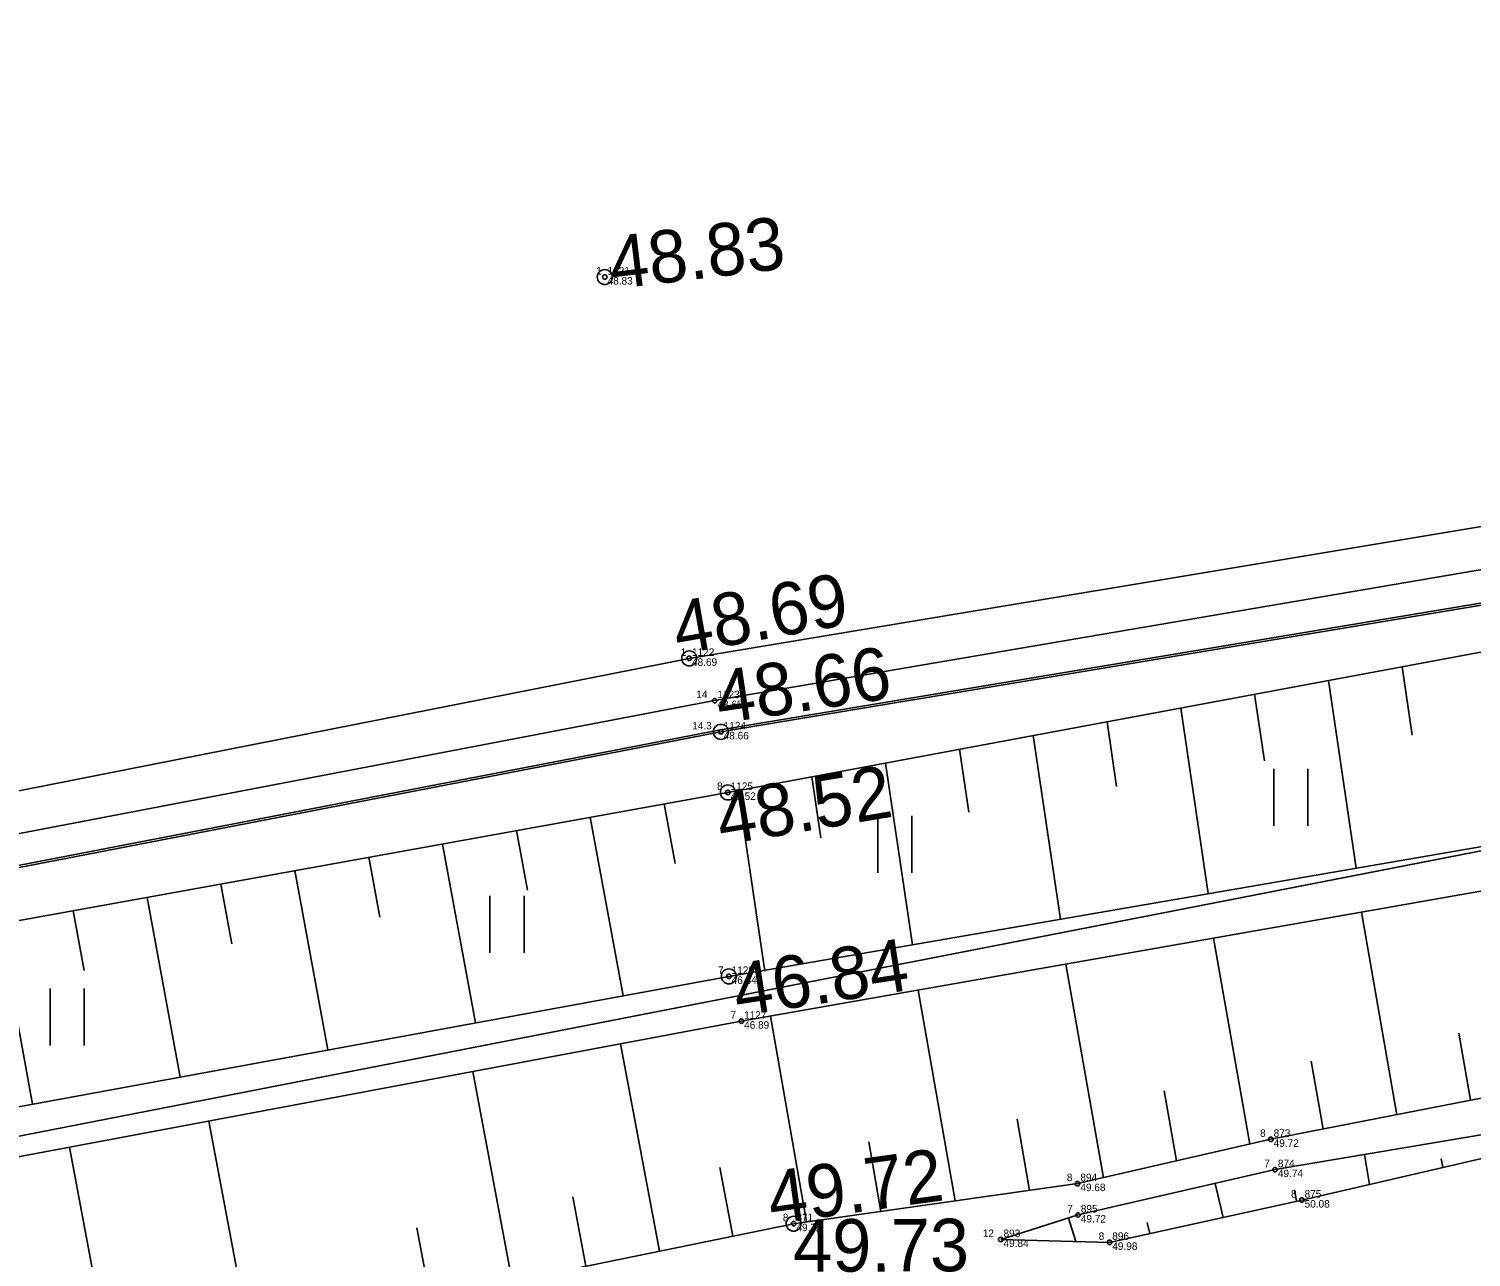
# Model space of a CAD drawing. Extents: x 543497 to 552146, y 6567125 to 6579845.
# Drawn here: x 546549.56 to 546568.77, y 6577774.51 to 6577790.87 of the extents above; entities that cross this region are included whole.
import ezdxf

# ---------------------------------------------------------------- set-up
doc = ezdxf.new("R2010")
doc.units = 0
for name, color, linetype in [('xref_Kangru tee 1_geodeesia$0$HALJASTUS', 7, 'Continuous'), ('xref_Kangru tee 1_geodeesia$0$korgus-EH2000', 7, 'Continuous'), ('xref_Kangru tee 1_geodeesia$0$Liiklus', 7, 'Continuous'), ('xref_Kangru tee 1_geodeesia$0$mootkood', 7, 'Continuous'), ('xref_Kangru tee 1_geodeesia$0$MOOTKORG-eh2000', 7, 'Continuous'), ('xref_Kangru tee 1_geodeesia$0$mootmpunkt', 7, 'Continuous'), ('xref_Kangru tee 1_geodeesia$0$MOOTNR', 7, 'Continuous'), ('xref_Kangru tee 1_geodeesia$0$PIIR', 7, 'Continuous'), ('xref_Kangru tee 1_geodeesia$0$RELJEEF', 7, 'Continuous'), ('xref_Kangru tee 1_geodeesia$0$TEE', 7, 'Continuous')]:
    doc.layers.add(name, color=color, linetype=linetype)

# ---------------------------------------------------------------- blocks, each defined once
blk = doc.blocks.new('xref_Kangru tee 1_geodeesia$0$hein')
for p, q in [((-0.455, 0.761), (-0.455, -0.761)), ((0.455, 0.761), (0.455, -0.761))]:
    blk.add_line(p, q)

msp = doc.modelspace()

# ---------------------------------------------------------------- linework, layer by layer
at = {"layer": 'xref_Kangru tee 1_geodeesia$0$korgus-EH2000'}
for centre in [(546557.23, 6577787.563), (546558.355, 6577782.483), (546558.777, 6577781.504), (546558.87, 6577780.697), (546558.883, 6577778.247), (546559.746, 6577774.952)]:
    msp.add_circle(centre, 0.1, dxfattribs=at)
at = {"layer": 'xref_Kangru tee 1_geodeesia$0$Liiklus'}
for points in [[(546721.913, 6577774.924), (546704.498, 6577780.481), (546687.619, 6577784.545), (546672.912, 6577787.228), (546667.133, 6577788), (546648.703, 6577789.664), (546634.507, 6577790.018), (546619.416, 6577789.618), (546613.24, 6577789.23), (546599.919, 6577788.183), (546580.395, 6577785.626), (546558.693, 6577781.92), (546538.215, 6577778.009)], [(546538.26, 6577777.571), (546558.77, 6577781.533), (546580.893, 6577785.218), (546600.058, 6577787.695), (546613.274, 6577788.837)]]:
    msp.add_lwpolyline(points, dxfattribs=at)
at = {"layer": 'xref_Kangru tee 1_geodeesia$0$mootmpunkt'}
for centre in [(546557.23, 6577787.563), (546558.355, 6577782.483), (546558.693, 6577781.92), (546558.777, 6577781.504), (546558.87, 6577780.697), (546558.883, 6577778.247), (546559.049, 6577777.65), (546566.104, 6577776.076), (546566.16, 6577775.672), (546563.529, 6577775.486), (546566.516, 6577775.267), (546563.535, 6577775.068), (546559.746, 6577774.952), (546562.505, 6577774.741), (546563.954, 6577774.703)]:
    msp.add_circle(centre, 0.03, dxfattribs=at)
at = {"layer": 'xref_Kangru tee 1_geodeesia$0$PIIR'}
for points in [[(546508.03, 6577841.48), (546527.76, 6577842.6), (546535.64, 6577829.79), (546540.71, 6577817.81), (546551.12, 6577809.99), (546561.59, 6577802.16), (546622.52, 6577814.88), (546633.51, 6577792.62), (546608.95, 6577787.91), (546573.78, 6577780.87), (546521.59, 6577770.69), (546316.12, 6577725.86), (546173.38, 6577691.06), (546034.23, 6577654.21), (545899.95, 6577611.29), (545780.54, 6577566.57), (545623.97, 6577499.02), (545555.77, 6577467.67), (545385.83, 6577376.92), (545249.19, 6577295.85), (545250.22, 6577289.9), (544980.83, 6577118.49)], [(546741.41, 6577111.25), (546683.61, 6577317.78), (546673.81, 6577353.39), (546663.96, 6577389.17), (546660.51, 6577401.7), (546647.19, 6577450.09), (546634.65, 6577495.62), (546625.43, 6577526.07), (546609.43, 6577571.52), (546593.21, 6577617.62), (546579.42, 6577656.79), (546562.86, 6577702.03), (546544.17, 6577758.03), (546521.59, 6577770.69), (546573.78, 6577780.87), (546573.57, 6577772.24), (546572.44, 6577729.89), (546568.55, 6577727.96), (546603, 6577632.08), (546611.62, 6577607.53), (546638.72, 6577530.39), (546648.14, 6577499.5), (546658.9, 6577460.58), (546749.51, 6577130.19)]]:
    msp.add_lwpolyline(points, dxfattribs=at)
at = {"layer": 'xref_Kangru tee 1_geodeesia$0$RELJEEF'}
for p, q in [((546567.853, 6577782.371), (546567.988, 6577781.459)), ((546566.87, 6577782.188), (546567.24, 6577779.689)), ((546565.887, 6577782.005), (546566.018, 6577781.117)), ((546564.904, 6577781.821), (546565.27, 6577779.349)), ((546563.921, 6577781.638), (546564.049, 6577780.775)), ((546562.938, 6577781.455), (546563.3, 6577779.009)), ((546561.955, 6577781.272), (546562.079, 6577780.434)), ((546560.971, 6577781.089), (546561.33, 6577778.669)), ((546559.988, 6577780.905), (546560.109, 6577780.092)), ((546559.005, 6577780.722), (546559.361, 6577778.318)), ((546558.021, 6577780.544), (546558.167, 6577779.752)), ((546557.037, 6577780.366), (546557.474, 6577777.988)), ((546556.053, 6577780.188), (546556.199, 6577779.395)), ((546555.069, 6577780.01), (546555.506, 6577777.627)), ((546554.085, 6577779.833), (546554.231, 6577779.037)), ((546553.101, 6577779.655), (546553.539, 6577777.266)), ((546551.133, 6577779.299), (546551.572, 6577776.905)), ((546552.117, 6577779.477), (546552.263, 6577778.68)), ((546550.149, 6577779.121), (546550.295, 6577778.323)), ((546567.784, 6577776.404), (546567.31, 6577779.102)), ((546549.165, 6577778.944), (546549.605, 6577776.544)), ((546565.823, 6577776.012), (546565.341, 6577778.756)), ((546563.873, 6577775.565), (546563.373, 6577778.41)), ((546561.898, 6577775.256), (546561.405, 6577778.064)), ((546559.918, 6577774.976), (546559.436, 6577777.718)), ((546568.765, 6577776.596), (546568.608, 6577777.489)), ((546557.957, 6577774.585), (546557.439, 6577777.348)), ((546566.802, 6577776.212), (546566.643, 6577777.118)), ((546555.998, 6577774.184), (546555.474, 6577776.98)), ((546564.848, 6577775.788), (546564.684, 6577776.72)), ((546552.749, 6577772.083), (546551.954, 6577776.32)), ((546562.889, 6577775.396), (546562.722, 6577776.343)), ((546560.908, 6577775.116), (546560.746, 6577776.041)), ((546551.012, 6577771.109), (546550.1, 6577775.972)), ((546567.419, 6577775.476), (546567.352, 6577775.873)), ((546558.937, 6577774.786), (546558.765, 6577775.702)), ((546568.394, 6577775.701), (546568.375, 6577775.814)), ((546565.468, 6577775.036), (546565.364, 6577775.489)), ((546556.977, 6577774.385), (546556.804, 6577775.311)), ((546566.445, 6577775.251), (546566.419, 6577775.403)), ((546554.904, 6577773.96), (546554.728, 6577774.898)), ((546563.505, 6577774.715), (546563.406, 6577775.027)), ((546564.492, 6577774.821), (546564.458, 6577774.969))]:
    msp.add_line(p, q, dxfattribs=at)
for points in [[(546538.34, 6577776.988), (546558.87, 6577780.697), (546581.001, 6577784.821), (546600.069, 6577787.156), (546619.252, 6577788.758)], [(546538.814, 6577774.564), (546558.883, 6577778.247), (546581.357, 6577782.125), (546600.081, 6577784.554), (546618.535, 6577786.262), (546633.012, 6577786.921), (546648.115, 6577786.579), (546666.374, 6577784.262), (546672.405, 6577783.73), (546686.612, 6577781.238), (546689.643, 6577780.706), (546693.637, 6577779.753), (546703.929, 6577777.342), (546710.71, 6577775.098), (546720.871, 6577771.555)], [(546538.896, 6577773.872), (546559.049, 6577777.65), (546581.571, 6577781.608), (546600.058, 6577784.083), (546618.575, 6577785.829), (546632.878, 6577786.269), (546648.145, 6577785.891), (546666.337, 6577783.931), (546672.337, 6577783.228), (546686.505, 6577780.733), (546689.529, 6577780.165), (546693.523, 6577779.183), (546703.735, 6577776.88), (546710.628, 6577774.799), (546720.7, 6577771.177)], [(546554.904, 6577773.96), (546559.746, 6577774.952), (546563.529, 6577775.486), (546566.104, 6577776.076), (546569.451, 6577776.73), (546575.285, 6577777.669), (546591.928, 6577780.074), (546609.002, 6577782.024), (546618.326, 6577782.861), (546622.722, 6577782.991), (546628.579, 6577783.379), (546640.222, 6577783.284), (546642.311, 6577782.972), (546644.296, 6577782.453), (546645.105, 6577782.242), (546655.773, 6577781.108), (546661.524, 6577780.531), (546663.681, 6577779.627)], [(546575.259, 6577776.901), (546574.683, 6577777.021), (546570.092, 6577776.335), (546566.16, 6577775.672), (546563.535, 6577775.068), (546562.505, 6577774.741)], [(546562.505, 6577774.741), (546563.954, 6577774.703), (546566.516, 6577775.267), (546569.817, 6577776.03), (546574.641, 6577776.578), (546575.259, 6577776.901)]]:
    msp.add_lwpolyline(points, dxfattribs=at)
at = {"layer": 'xref_Kangru tee 1_geodeesia$0$TEE'}
for points in [[(546538.072, 6577778.474), (546558.355, 6577782.483), (546580.018, 6577786.09), (546599.801, 6577788.666), (546619.258, 6577790.187), (546634.544, 6577790.675), (546648.905, 6577790.198), (546667.188, 6577788.59), (546673.08, 6577787.807), (546687.848, 6577785.135), (546704.62, 6577781.061), (546722.283, 6577775.399)], [(546704.364, 6577779.548), (546687.303, 6577783.754), (546672.831, 6577786.155), (546666.989, 6577786.944), (546648.576, 6577788.953), (546634.52, 6577789.12), (546619.252, 6577788.758), (546600.059, 6577787.667), (546580.898, 6577785.19), (546558.777, 6577781.504), (546538.268, 6577777.542)]]:
    msp.add_lwpolyline(points, dxfattribs=at)

# ---------------------------------------------------------------- block references
at = {"layer": 'xref_Kangru tee 1_geodeesia$0$HALJASTUS', "xscale": 0.5, "yscale": 0.5}
for p in [(546566.37, 6577780.633), (546561.094, 6577780.005), (546555.928, 6577778.94), (546550.068, 6577777.706)]:
    msp.add_blockref('xref_Kangru tee 1_geodeesia$0$hein', p, dxfattribs=at)

# ---------------------------------------------------------------- texts
at = {"layer": 'xref_Kangru tee 1_geodeesia$0$korgus-EH2000'}
for s, rotation, p in [(' 48.83 ', 6.8905, (546557.076, 6577787.368)), (' 48.69 ', 10.0743, (546557.949, 6577782.486)), (' 48.66 ', 8.4543, (546558.504, 6577781.574)), (' 48.52 ', 9.5, (546558.526, 6577779.949)), (' 46.84 ', 8.7462, (546558.741, 6577777.672)), (' 49.72 ', 7.9356, (546559.194, 6577774.908)), (' 49.73 ', 0.2292, (546559.481, 6577774.309))]:
    msp.add_text(s, height=0.7, rotation=rotation, dxfattribs=at).set_placement(p)
at = {"layer": 'xref_Kangru tee 1_geodeesia$0$mootkood'}
for s, p in [(' 1', (546557.078, 6577787.596)), (' 1', (546558.203, 6577782.516)), (' 14', (546558.412, 6577781.953)), (' 14.3', (546558.358, 6577781.537)), (' 8', (546558.689, 6577780.73)), (' 7', (546558.702, 6577778.28)), (' 7', (546558.868, 6577777.683)), (' 8', (546565.923, 6577776.109)), (' 7', (546565.979, 6577775.705)), (' 8', (546563.348, 6577775.519)), (' 8', (546566.335, 6577775.3)), (' 8', (546559.565, 6577774.985)), (' 7', (546563.354, 6577775.101)), (' 12', (546562.229, 6577774.774)), (' 8', (546563.773, 6577774.736))]:
    msp.add_text(s, height=0.1, dxfattribs=at).set_placement(p)
at = {"layer": 'xref_Kangru tee 1_geodeesia$0$MOOTKORG-eh2000'}
for s, p in [(' 48.83', (546557.23, 6577787.463)), (' 48.69', (546558.355, 6577782.383)), (' 48.65', (546558.693, 6577781.82)), (' 48.66', (546558.777, 6577781.404)), (' 48.52', (546558.87, 6577780.597)), (' 46.84', (546558.883, 6577778.147)), (' 46.89', (546559.049, 6577777.55)), (' 49.72', (546566.104, 6577775.976)), (' 49.74', (546566.16, 6577775.572)), (' 49.68', (546563.529, 6577775.386)), (' 50.08', (546566.516, 6577775.167)), (' 49.72', (546563.535, 6577774.968)), (' 49.72', (546559.746, 6577774.852)), (' 49.84', (546562.505, 6577774.641)), (' 49.98', (546563.954, 6577774.603))]:
    msp.add_text(s, height=0.1, dxfattribs=at).set_placement(p)
at = {"layer": 'xref_Kangru tee 1_geodeesia$0$MOOTNR'}
for s, p in [(' 1121', (546557.23, 6577787.596)), (' 1122', (546558.355, 6577782.516)), (' 1123', (546558.693, 6577781.953)), (' 1124', (546558.777, 6577781.537)), (' 1125', (546558.87, 6577780.73)), (' 1126', (546558.883, 6577778.28)), (' 1127', (546559.049, 6577777.683)), (' 873', (546566.104, 6577776.109)), (' 874', (546566.16, 6577775.705)), (' 894', (546563.529, 6577775.519)), (' 875', (546566.516, 6577775.3)), (' 871', (546559.746, 6577774.985)), (' 895', (546563.535, 6577775.101)), (' 893', (546562.505, 6577774.774)), (' 896', (546563.954, 6577774.736))]:
    msp.add_text(s, height=0.1, dxfattribs=at).set_placement(p)

doc.saveas('drawing.dxf')
